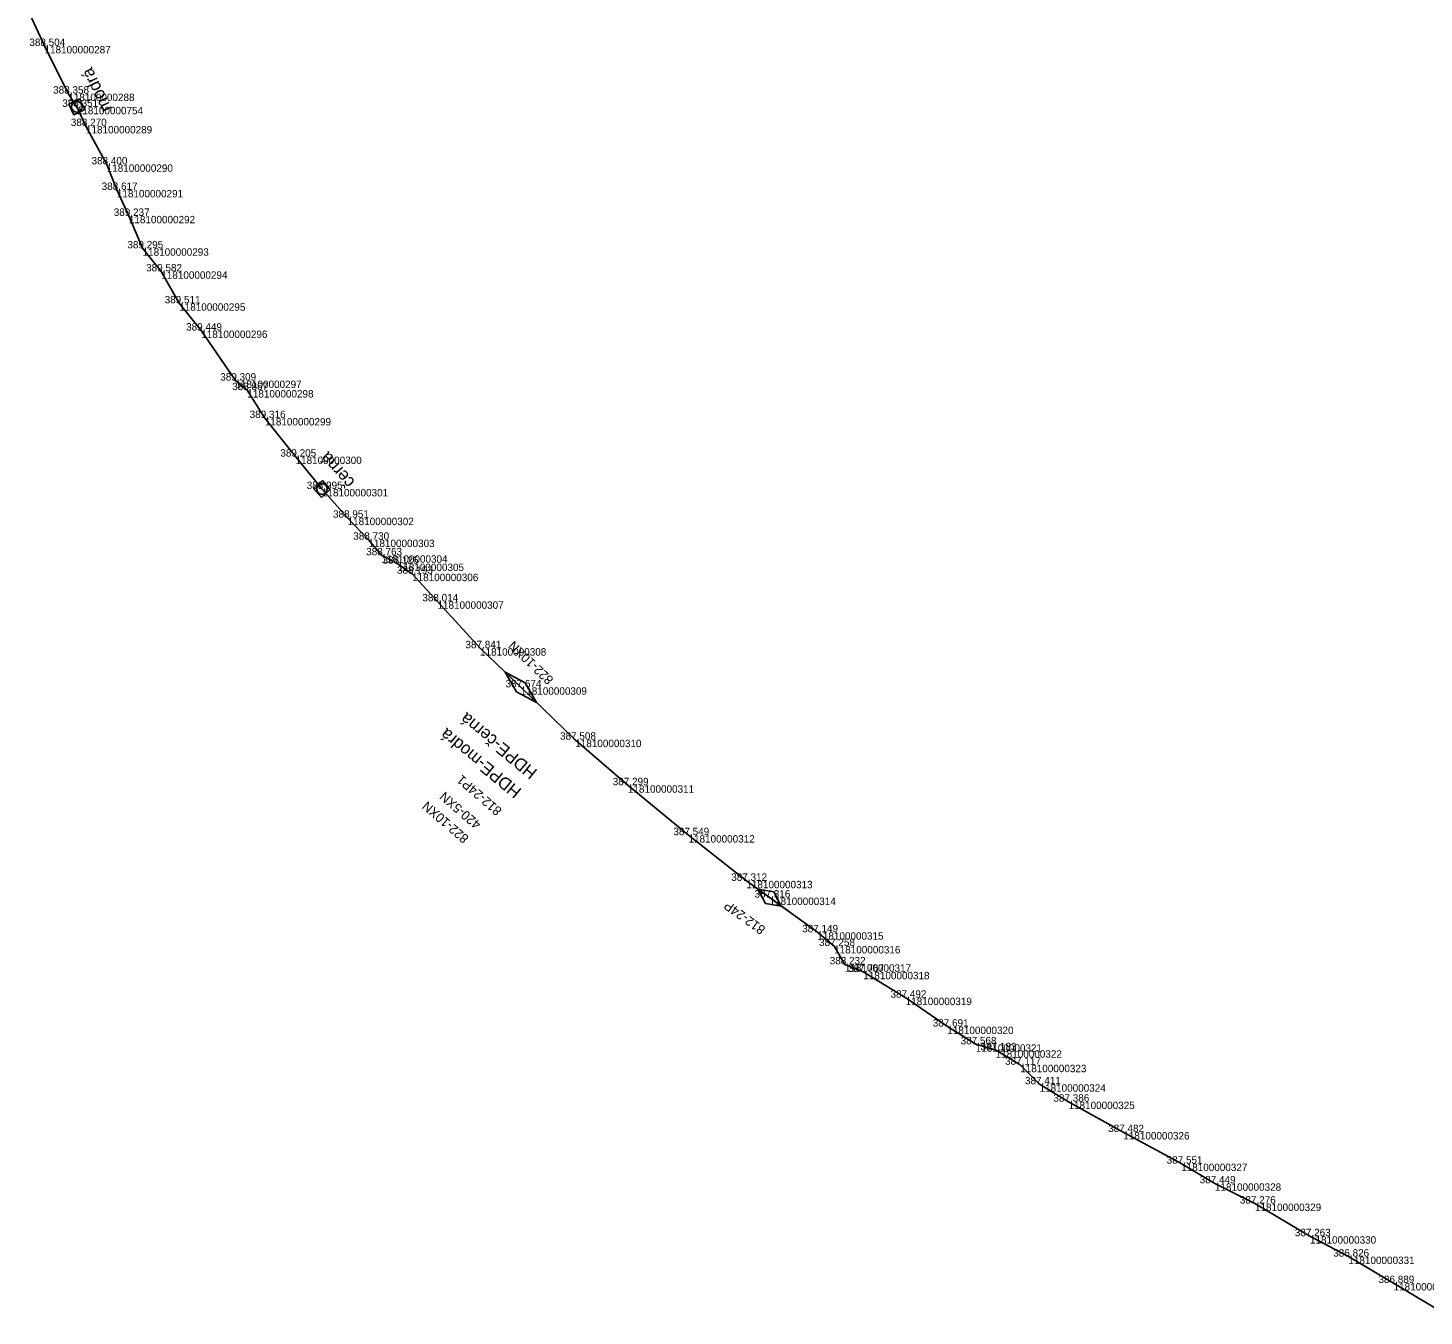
# Model space of a CAD drawing. Extents: x -724084 to -720954, y -948423 to -945131.
# Drawn here: x -721904.4 to -721678.5, y -947807.1 to -947598.7 of the extents above; entities that cross this region are included whole.
import ezdxf

# ---------------------------------------------------------------- set-up
doc = ezdxf.new("R2010")
doc.units = 0
for name, color, linetype in [('Vrstva 28', 7, 'Continuous'), ('Vrstva 31', 7, 'Continuous'), ('Vrstva 33', 7, 'Continuous'), ('Vrstva 60', 7, 'Continuous'), ('Vrstva 61', 7, 'Continuous')]:
    doc.layers.add(name, color=color, linetype=linetype)

msp = doc.modelspace()

# ---------------------------------------------------------------- linework, layer by layer
at = {"layer": 'Vrstva 28'}
for p, q in [((-721781.58, -947741.46), (-721787.22, -947737.36)), ((-721785.08, -947740.35), (-721786.28, -947738.04)), ((-721786.28, -947738.04), (-721783.72, -947738.47)), ((-721782.52, -947740.78), (-721785.08, -947740.35)), ((-721783.72, -947738.47), (-721782.52, -947740.78))]:
    msp.add_line(p, q, dxfattribs=at)
msp.add_lwpolyline([(-721674.53, -947807.12), (-721683.46, -947801.78), (-721690.77, -947797.5), (-721696.99, -947794.2), (-721705.88, -947788.92), (-721712.36, -947785.65), (-721717.82, -947782.46), (-721727.18, -947777.35), (-721736.04, -947772.43), (-721740.73, -947769.62), (-721743.86, -947766.46), (-721747.83, -947764.11), (-721751.05, -947763.15), (-721755.65, -947760.29), (-721762.39, -947755.61), (-721769.24, -947751.43), (-721772.23, -947750.21), (-721773.95, -947747.25), (-721776.68, -947745.02), (-721784.4, -947739.41), (-721788.16, -947736.7), (-721797.52, -947729.31), (-721807.32, -947721.23), (-721815.84, -947713.86), (-721824.66, -947705.39), (-721831.24, -947699.06), (-721838.13, -947691.48), (-721842.23, -947687.01), (-721844.55, -947685.39), (-721847.21, -947684.03), (-721849.3, -947681.5), (-721852.67, -947677.95), (-721856.82, -947673.3), (-721861.09, -947668.06), (-721866.06, -947661.82), (-721868.89, -947657.3), (-721870.81, -947655.76), (-721876.34, -947647.67), (-721879.91, -947643.26), (-721882.81, -947638.09), (-721885.83, -947634.36), (-721888.05, -947629.11), (-721889.99, -947624.91), (-721891.64, -947620.78), (-721894.99, -947614.57), (-721896.47, -947611.47), (-721897.85, -947609.33), (-721901.7, -947601.62), (-721904.38, -947595.77)], dxfattribs=at)
at = {"layer": 'Vrstva 31'}
for points in [[(-721674.53, -947807.12), (-721683.46, -947801.78), (-721690.77, -947797.5), (-721696.99, -947794.2), (-721705.88, -947788.92), (-721712.36, -947785.65), (-721717.82, -947782.46), (-721727.18, -947777.35), (-721736.04, -947772.43), (-721740.73, -947769.62), (-721743.86, -947766.46), (-721747.83, -947764.11), (-721751.05, -947763.15), (-721755.65, -947760.29), (-721762.39, -947755.61), (-721769.24, -947751.43), (-721772.23, -947750.21), (-721773.95, -947747.25), (-721776.68, -947745.02), (-721784.4, -947739.41), (-721788.16, -947736.7), (-721797.52, -947729.31), (-721807.32, -947721.23), (-721815.84, -947713.86), (-721824.66, -947705.39), (-721831.24, -947699.06), (-721838.13, -947691.48), (-721842.23, -947687.01), (-721844.55, -947685.39), (-721847.21, -947684.03), (-721849.3, -947681.5), (-721852.67, -947677.95), (-721856.82, -947673.3), (-721861.09, -947668.06), (-721866.06, -947661.82), (-721868.89, -947657.3), (-721870.81, -947655.76), (-721876.34, -947647.67), (-721879.91, -947643.26), (-721882.81, -947638.09), (-721885.83, -947634.36), (-721888.05, -947629.11), (-721889.99, -947624.91), (-721891.64, -947620.78), (-721894.99, -947614.57), (-721896.47, -947611.47), (-721897.85, -947609.33), (-721901.7, -947601.62), (-721904.38, -947595.77)], [(-721822.13, -947707.82), (-721825.35, -947706.11), (-721827.18, -947702.96), (-721823.96, -947704.67), (-721822.13, -947707.82)]]:
    msp.add_lwpolyline(points, dxfattribs=at)
at = {"layer": 'Vrstva 33'}
msp.add_lwpolyline([(-721674.53, -947807.12), (-721683.46, -947801.78), (-721690.77, -947797.5), (-721696.99, -947794.2), (-721705.88, -947788.92), (-721712.36, -947785.65), (-721717.82, -947782.46), (-721727.18, -947777.35), (-721736.04, -947772.43), (-721740.73, -947769.62), (-721743.86, -947766.46), (-721747.83, -947764.11), (-721751.05, -947763.15), (-721755.65, -947760.29), (-721762.39, -947755.61), (-721769.24, -947751.43), (-721772.23, -947750.21), (-721773.95, -947747.25), (-721776.68, -947745.02), (-721784.4, -947739.41), (-721788.16, -947736.7), (-721797.52, -947729.31), (-721807.32, -947721.23), (-721815.84, -947713.86), (-721824.66, -947705.39), (-721831.24, -947699.06), (-721838.13, -947691.48), (-721842.23, -947687.01), (-721844.55, -947685.39), (-721847.21, -947684.03), (-721849.3, -947681.5), (-721852.67, -947677.95), (-721856.82, -947673.3), (-721861.09, -947668.06), (-721866.06, -947661.82), (-721868.89, -947657.3), (-721870.81, -947655.76), (-721876.34, -947647.67), (-721879.91, -947643.26), (-721882.81, -947638.09), (-721885.83, -947634.36), (-721888.05, -947629.11), (-721889.99, -947624.91), (-721891.64, -947620.78), (-721894.99, -947614.57), (-721896.47, -947611.47), (-721897.85, -947609.33), (-721901.7, -947601.62), (-721904.38, -947595.77)], dxfattribs=at)
for points in [[(-721895.19, -947611.92), (-721896.02, -947610.19), (-721897.76, -947611.01), (-721896.93, -947612.75)], [(-721855.47, -947673.37), (-721856.74, -947671.94), (-721858.18, -947673.22), (-721856.9, -947674.65)]]:
    msp.add_lwpolyline(points, close=True, dxfattribs=at)
for centre in [(-721896.47, -947611.47), (-721856.82, -947673.3)]:
    msp.add_circle(centre, 0.864, dxfattribs=at)
at = {"layer": 'Vrstva 60'}
for p, q in [((-721901.7, -947601.62), (-721901.7, -947601.62)), ((-721897.85, -947609.33), (-721897.85, -947609.33)), ((-721896.47, -947611.47), (-721896.47, -947611.47)), ((-721894.99, -947614.57), (-721894.99, -947614.57)), ((-721891.64, -947620.78), (-721891.64, -947620.78)), ((-721889.99, -947624.91), (-721889.99, -947624.91)), ((-721888.05, -947629.11), (-721888.05, -947629.11)), ((-721885.83, -947634.36), (-721885.83, -947634.36)), ((-721882.81, -947638.09), (-721882.81, -947638.09)), ((-721879.91, -947643.26), (-721879.91, -947643.26)), ((-721876.34, -947647.67), (-721876.34, -947647.67)), ((-721870.81, -947655.76), (-721870.81, -947655.76)), ((-721868.89, -947657.3), (-721868.89, -947657.3)), ((-721866.06, -947661.82), (-721866.06, -947661.82)), ((-721861.09, -947668.06), (-721861.09, -947668.06)), ((-721856.82, -947673.3), (-721856.82, -947673.3)), ((-721852.67, -947677.95), (-721852.67, -947677.95)), ((-721849.3, -947681.5), (-721849.3, -947681.5)), ((-721847.21, -947684.03), (-721847.21, -947684.03)), ((-721844.55, -947685.39), (-721844.55, -947685.39)), ((-721842.23, -947687.01), (-721842.23, -947687.01)), ((-721838.13, -947691.48), (-721838.13, -947691.48)), ((-721831.24, -947699.06), (-721831.24, -947699.06)), ((-721824.66, -947705.39), (-721824.66, -947705.39)), ((-721815.84, -947713.86), (-721815.84, -947713.86)), ((-721807.32, -947721.23), (-721807.32, -947721.23)), ((-721797.52, -947729.31), (-721797.52, -947729.31)), ((-721788.16, -947736.7), (-721788.16, -947736.7)), ((-721784.4, -947739.41), (-721784.4, -947739.41)), ((-721776.68, -947745.02), (-721776.68, -947745.02)), ((-721773.95, -947747.25), (-721773.95, -947747.25)), ((-721772.23, -947750.21), (-721772.23, -947750.21)), ((-721769.24, -947751.43), (-721769.24, -947751.43)), ((-721762.39, -947755.61), (-721762.39, -947755.61)), ((-721755.65, -947760.29), (-721755.65, -947760.29)), ((-721751.05, -947763.15), (-721751.05, -947763.15)), ((-721747.83, -947764.11), (-721747.83, -947764.11)), ((-721743.86, -947766.46), (-721743.86, -947766.46)), ((-721740.73, -947769.62), (-721740.73, -947769.62)), ((-721736.04, -947772.43), (-721736.04, -947772.43)), ((-721727.18, -947777.35), (-721727.18, -947777.35)), ((-721717.82, -947782.46), (-721717.82, -947782.46)), ((-721712.36, -947785.65), (-721712.36, -947785.65)), ((-721705.88, -947788.92), (-721705.88, -947788.92)), ((-721696.99, -947794.2), (-721696.99, -947794.2)), ((-721690.77, -947797.5), (-721690.77, -947797.5)), ((-721683.46, -947801.78), (-721683.46, -947801.78))]:
    msp.add_line(p, q, dxfattribs=at)

# ---------------------------------------------------------------- texts
at = {"layer": 'Vrstva 28'}
for s, rotation, p in [('812-24P1', 139.1428, (-721827.6, -947725.15)), ('812-24P', 144.0075, (-721784.95, -947744.3))]:
    msp.add_text(s, height=1.5, rotation=rotation, dxfattribs=at).set_placement(p)
at = {"layer": 'Vrstva 31'}
for s, rotation, p in [('822-10XN', 136.1202, (-721819.25, -947704.02)), ('420-5XN', 139.1428, (-721830.97, -947727.36)), ('822-10XN', 139.1428, (-721832.94, -947729.63))]:
    msp.add_text(s, height=1.5, rotation=rotation, dxfattribs=at).set_placement(p)
at = {"layer": 'Vrstva 33'}
for s, rotation, p in [('modrá', 115.5815, (-721890.79, -947611.77)), ('černá', 131.7258, (-721851.38, -947672.1)), ('HDPE-černá', 140.5345, (-721821.84, -947718.88)), ('HDPE-modrá', 140.5345, (-721824.38, -947721.97))]:
    msp.add_text(s, height=2, rotation=rotation, dxfattribs=at).set_placement(p)
at = {"layer": 'Vrstva 60'}
for s, p in [('118100000287', (-721901.7, -947602.82)), ('118100000288', (-721897.85, -947610.53)), ('118100000754', (-721896.47, -947612.67)), ('118100000289', (-721894.99, -947615.77)), ('118100000290', (-721891.64, -947621.98)), ('118100000291', (-721889.99, -947626.11)), ('118100000292', (-721888.05, -947630.31)), ('118100000293', (-721885.83, -947635.56)), ('118100000294', (-721882.81, -947639.29)), ('118100000295', (-721879.91, -947644.46)), ('118100000296', (-721876.34, -947648.87)), ('118100000297', (-721870.81, -947656.96)), ('118100000298', (-721868.89, -947658.5)), ('118100000299', (-721866.06, -947663.02)), ('118100000300', (-721861.09, -947669.26)), ('118100000301', (-721856.82, -947674.5)), ('118100000302', (-721852.67, -947679.15)), ('118100000303', (-721849.3, -947682.7)), ('118100000304', (-721847.21, -947685.23)), ('118100000305', (-721844.55, -947686.58)), ('118100000306', (-721842.23, -947688.21)), ('118100000307', (-721838.13, -947692.68)), ('118100000308', (-721831.24, -947700.26)), ('118100000309', (-721824.66, -947706.59)), ('118100000310', (-721815.84, -947715.07)), ('118100000311', (-721807.32, -947722.44)), ('118100000312', (-721797.52, -947730.51)), ('118100000313', (-721788.16, -947737.9)), ('118100000314', (-721784.4, -947740.61)), ('118100000315', (-721776.68, -947746.22)), ('118100000316', (-721773.95, -947748.45)), ('118100000317', (-721772.23, -947751.41)), ('118100000318', (-721769.24, -947752.63)), ('118100000319', (-721762.39, -947756.81)), ('118100000320', (-721755.65, -947761.49)), ('118100000321', (-721751.05, -947764.35)), ('118100000322', (-721747.83, -947765.31)), ('118100000323', (-721743.86, -947767.66)), ('118100000324', (-721740.73, -947770.82)), ('118100000325', (-721736.04, -947773.63)), ('118100000326', (-721727.18, -947778.55)), ('118100000327', (-721717.82, -947783.66)), ('118100000328', (-721712.36, -947786.85)), ('118100000329', (-721705.88, -947790.12)), ('118100000330', (-721696.99, -947795.4)), ('118100000331', (-721690.77, -947798.7)), ('118100000332', (-721683.46, -947802.98))]:
    msp.add_text(s, height=1.2, dxfattribs=at).set_placement(p)
at = {"layer": 'Vrstva 61'}
for s, p in [('388.504', (-721904.15, -947601.62)), ('388.358', (-721900.3, -947609.33)), ('388.351', (-721898.83, -947611.47)), ('388.270', (-721897.44, -947614.57)), ('388.400', (-721894.09, -947620.78)), ('388.617', (-721892.45, -947624.91)), ('389.237', (-721890.5, -947629.11)), ('389.295', (-721888.29, -947634.36)), ('389.582', (-721885.26, -947638.09)), ('389.511', (-721882.26, -947643.26)), ('389.449', (-721878.79, -947647.67)), ('389.309', (-721873.27, -947655.76)), ('388.867', (-721871.34, -947657.3)), ('389.316', (-721868.51, -947661.82)), ('389.205', (-721863.55, -947668.06)), ('388.995', (-721859.28, -947673.3)), ('388.951', (-721855.03, -947677.95)), ('388.730', (-721851.75, -947681.5)), ('388.763', (-721849.66, -947684.03)), ('388.126', (-721847.01, -947685.39)), ('388.193', (-721844.68, -947687.01)), ('388.014', (-721840.58, -947691.48)), ('387.841', (-721833.6, -947699.06)), ('387.674', (-721827.11, -947705.39)), ('387.508', (-721818.3, -947713.86)), ('387.299', (-721809.78, -947721.23)), ('387.549', (-721799.97, -947729.31)), ('387.312', (-721790.61, -947736.7)), ('387.316', (-721786.85, -947739.41)), ('387.149', (-721779.13, -947745.02)), ('387.258', (-721776.4, -947747.25)), ('388.232', (-721774.67, -947750.21)), ('387.767', (-721771.7, -947751.43)), ('387.492', (-721764.84, -947755.61)), ('387.691', (-721758.01, -947760.29)), ('387.568', (-721753.5, -947763.15)), ('387.183', (-721750.28, -947764.11)), ('387.117', (-721746.31, -947766.46)), ('387.411', (-721743.09, -947769.62)), ('387.386', (-721738.49, -947772.43)), ('387.482', (-721729.63, -947777.35)), ('387.551', (-721720.17, -947782.46)), ('387.449', (-721714.82, -947785.65)), ('387.276', (-721708.33, -947788.92)), ('387.263', (-721699.44, -947794.2)), ('386.826', (-721693.22, -947797.5)), ('386.889', (-721685.91, -947801.78))]:
    msp.add_text(s, height=1.2, dxfattribs=at).set_placement(p)

doc.saveas('drawing.dxf')
